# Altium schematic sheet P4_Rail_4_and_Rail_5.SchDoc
size 368 x 228 mm
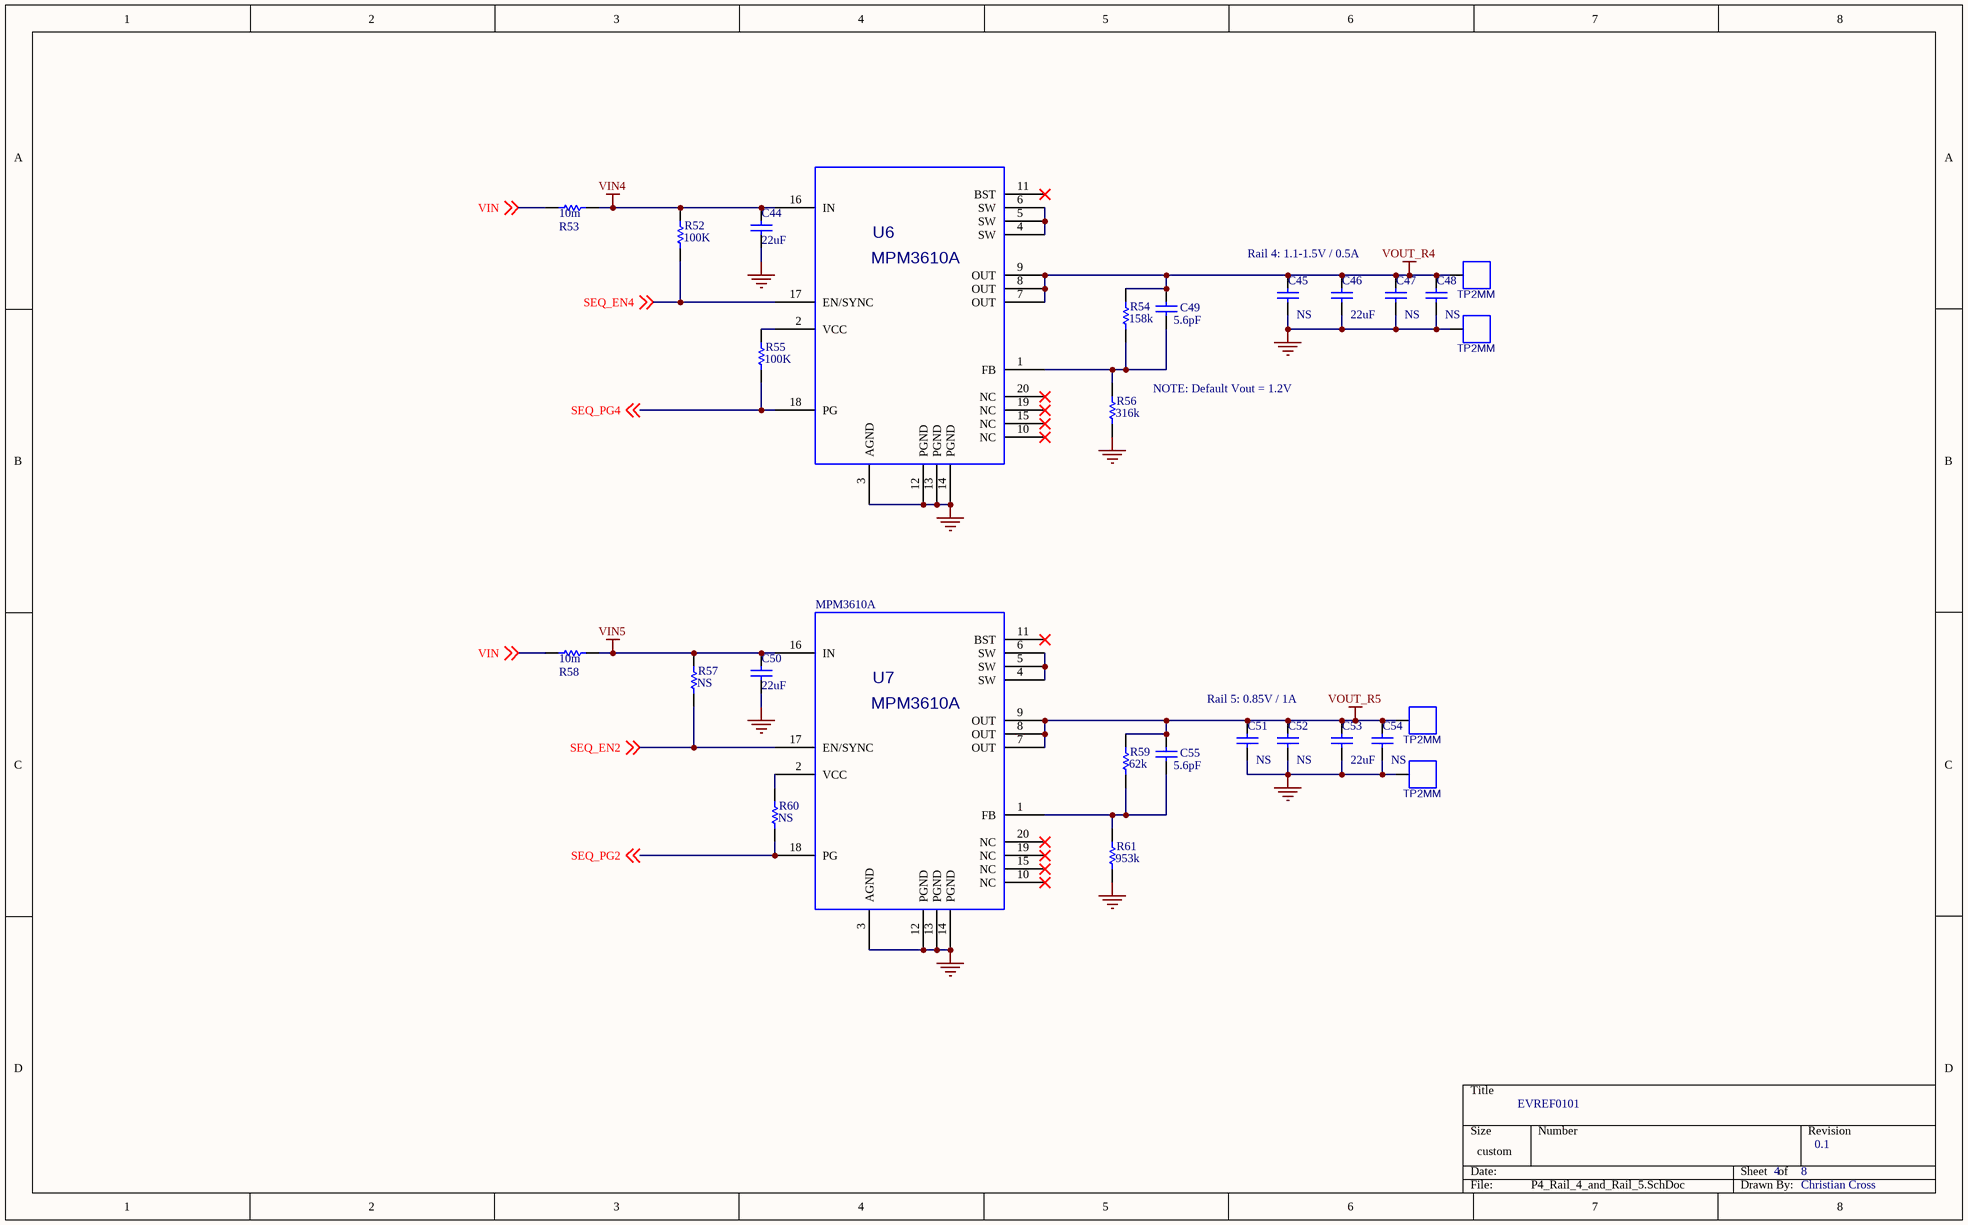
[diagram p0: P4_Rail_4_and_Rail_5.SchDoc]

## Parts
C44  22uF  [CAP0805]
C45  NS  [CAP0805]
C46  22uF  [CAP0805]
C47  NS  [CAP0805]
C48  NS  [CAP0805]
C49  5.6pF  [CAP/0603]
C50  22uF  [CAP0805]
C51  NS  [CAP0805]
C52  NS  [CAP0805]
C53  22uF  [CAP0805]
C54  NS  [CAP0805]
C55  5.6pF  [CAP/0603]
CN9  TP2MM  [TP2MM]
CN10  TP2MM  [TP2MM]
CN11  TP2MM  [TP2MM]
CN12  TP2MM  [TP2MM]
R52  value 100K  [RES/0603]  (hidden comment: 100k/RES0603)
R53  10m  [RES/0805]
R54  158k  [RES/0603]
R55  value 100K  [RES/0603]  (hidden comment: 100k/RES0603)
R56  value 316k  [RES/0603]  (hidden comment: 422k)
R57  value NS  [RES/0603]  (hidden comment: 100k/RES0603)
R58  10m  [RES/0805]
R59  value 62k  [RES/0603]  (hidden comment: 62k/RES0603)
R60  value NS  [RES/0603]  (hidden comment: 100k/RES0603)
R61  value 953k  [RES/0603]  (hidden comment: 953k/RES0603)
U6  MPM3610A  [QFN20-3X5MM]
U7  value MPM3610A  Manufacturer P/N: MPM3610A  [QFN20-3X5MM]  (hidden comment: MPM3630A)

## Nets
GND: C44.1 C45.1 C46.1 C47.1 C48.1 C50.1 C51.1 C52.1 C53.1 C54.1 CN10.1 CN12.1 R56.1 R61.1 U6.3(AGND) U6.12(PGND) U6.13(PGND) U6.14(PGND) U7.3(AGND) U7.12(PGND) U7.13(PGND) U7.14(PGND)
VIN4: C44.2 R52.2 R53.2 U6.16(IN)
VIN5: C50.2 R57.2 R58.2 U7.16(IN)
VOUT_R4: C45.2 C46.2 C47.2 C48.2 C49.2 CN9.1 R54.2 U6.7(OUT) U6.8(OUT) U6.9(OUT)
VOUT_R5: C51.2 C52.2 C53.2 C54.2 C55.2 CN11.1 R59.2 U7.7(OUT) U7.8(OUT) U7.9(OUT)
SEQ_EN2: R57.1 U7.17(EN/SYNC) ; off-sheet SEQ_EN2
SEQ_EN4: R52.1 U6.17(EN/SYNC) ; off-sheet SEQ_EN4
SEQ_PG2: R60.1 U7.18(PG) ; off-sheet SEQ_PG2
SEQ_PG4: R55.1 U6.18(PG) ; off-sheet SEQ_PG4
VIN: R53.1 R58.1 ; off-sheet VIN
NetC49_1: C49.1 R54.1 R56.2 U6.1(FB)
NetC55_1: C55.1 R59.1 R61.2 U7.1(FB)
NetR55_2: R55.2 U6.2(VCC)
NetR60_2: R60.2 U7.2(VCC)
NetU6_4: U6.4(SW) U6.5(SW) U6.6(SW)
NetU7_4: U7.4(SW) U7.5(SW) U7.6(SW)

Not connected (* = marked no-connect by the designer): U6 10(NC)* 11(BST)* 15(NC)* 19(NC)* 20(NC)*; U7 10(NC)* 11(BST)* 15(NC)* 19(NC)* 20(NC)*

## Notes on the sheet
- Rail 4: 1.1-1.5V / 0.5A
- NOTE: Default Vout = 1.2V
- Rail 5: 0.85V / 1A
- EVREF0101
- 4
- 8
- 0.1
- Christian Cross

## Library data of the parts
C44-C55 = Cap: Capacitor
CN9-CN12 = TP2MM: {Description}; Manufacturer: {Manufacturer}; Manufacturer P/N: {Manufacturer P/N}
R52 R54-R57 R59-R61 = Res1: Resistor
R53 R58 = Res1: Resistor; Value: 10mohm
U6 U7 = MPM3630A: 18V/3A DC/DC Module Synchronous Step-Down Regulator; Manufacturer: {Manufacturer}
